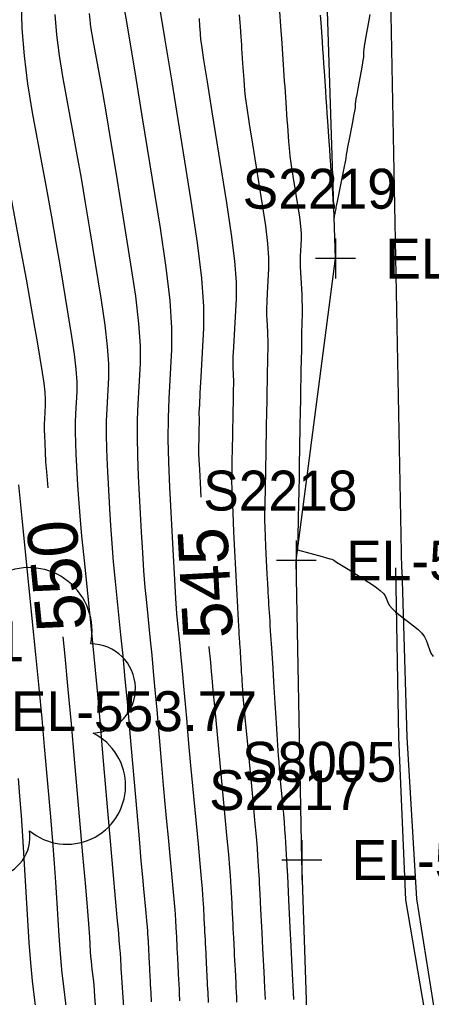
# Model space of a CAD drawing. Extents: x 1724534 to 1727318, y 657156 to 660047.
# Drawn here: x 1725500.6 to 1725541.9, y 658784.7 to 658882.6 of the extents above; entities that cross this region are included whole.
import ezdxf

# ---------------------------------------------------------------- set-up
doc = ezdxf.new("R2010")
doc.units = 0
for name, color, linetype in [('SURVEY - CONTOURS - Index with Text', 7, 'Continuous'), ('SURVEY - CONTOURS - Intermediate with optional Text', 7, 'Continuous'), ('SURVEY - DTM - Breaklines', 7, 'Continuous'), ('SURVEY - DTM - Breaklines - Points - Elevations', 7, 'Continuous'), ('SURVEY - DTM - Breaklines - Points - Locators', 7, 'Continuous'), ('SURVEY - DTM - Breaklines - Points - Numbers', 7, 'Continuous'), ('SURVEY - MISCELLANEOUS - Bottom of MH and CB - Points - Numbers', 7, 'Continuous'), ('SURVEY - UTILITIES - Electric (Underground) with Text', 7, 'Continuous'), ('SURVEY - UTILITIES - Fiber Optic Cable (Underground) with Text', 7, 'Continuous'), ('SURVEY - VEGETATION - Features - Points - Elevations', 7, 'Continuous'), ('SURVEY - VEGETATION - Features - Points - Numbers', 7, 'Continuous'), ('SURVEY - VEGETATION - Features with Text', 7, 'Continuous')]:
    doc.layers.add(name, color=color, linetype=linetype)

msp = doc.modelspace()

# ---------------------------------------------------------------- linework, layer by layer
at = {"layer": 'SURVEY - CONTOURS - Index with Text'}
for points in [[(1725497.421, 658883.779), (1725497.532, 658880.362), (1725497.804, 658876.878), (1725498.238, 658873.326), (1725498.833, 658869.706), (1725500.636, 658859.963), (1725501.251, 658856.622), (1725501.744, 658853.907), (1725502.114, 658851.818), (1725502.362, 658850.354), (1725502.859, 658847.284), (1725503.019, 658846.214), (1725503.125, 658845.305), (1725503.177, 658844.558), (1725503.176, 658843.973), (1725503.1, 658842.629), (1725503.08, 658842.099), (1725503.076, 658841.52), (1725503.089, 658840.891), (1725503.118, 658840.212), (1725503.217, 658838.334), (1725503.291, 658837.321), (1725503.432, 658835.734)], [(1725514.712, 658883.443), (1725515.174, 658880.583), (1725515.82, 658876.596), (1725517.787, 658864.461), (1725518.419, 658860.251), (1725518.842, 658856.721), (1725519.054, 658853.872), (1725519.056, 658851.703), (1725518.781, 658846.828), (1725518.691, 658845.218), (1725518.629, 658844.045), (1725518.593, 658843.31), (1725518.584, 658843.011), (1725518.596, 658842.799), (1725518.6, 658842.721), (1725518.603, 658842.645), (1725518.604, 658842.572), (1725518.603, 658842.502), (1725518.6, 658842.319), (1725518.598, 658842.249), (1725518.597, 658842.179), (1725518.596, 658842.106), (1725518.594, 658842.033), (1725518.591, 658841.835), (1725518.589, 658841.76), (1725518.588, 658841.683), (1725518.587, 658841.605), (1725518.585, 658841.525), (1725518.581, 658841.311), (1725518.58, 658841.229), (1725518.578, 658841.146), (1725518.577, 658841.061), (1725518.575, 658840.974), (1725518.571, 658840.741), (1725518.569, 658840.653), (1725518.568, 658840.562), (1725518.566, 658840.469), (1725518.564, 658840.375), (1725518.559, 658840.12), (1725518.558, 658840.023), (1725518.556, 658839.924), (1725518.554, 658839.823), (1725518.552, 658839.72), (1725518.547, 658839.44), (1725518.555, 658839.161), (1725518.582, 658838.534), (1725518.629, 658837.558), (1725518.696, 658836.234), (1725518.769, 658834.799)], [(1725504.937, 658820.809), (1725505.131, 658818.869), (1725505.452, 658815.535), (1725505.769, 658812.095), (1725506.084, 658808.551), (1725506.919, 658798.961), (1725507.197, 658795.747), (1725507.405, 658793.299), (1725507.543, 658791.616), (1725507.61, 658790.699), (1725507.694, 658789.273), (1725507.728, 658788.761), (1725507.765, 658788.293), (1725507.806, 658787.87), (1725507.851, 658787.491), (1725507.974, 658786.539), (1725508.036, 658785.918), (1725508.128, 658784.771), (1725508.252, 658783.096)], [(1725519.584, 658819.821), (1725519.629, 658819.379), (1725519.653, 658819.135), (1725519.679, 658818.864), (1725519.706, 658818.566), (1725519.735, 658818.24), (1725519.814, 658817.335), (1725519.873, 658816.685), (1725519.992, 658815.413), (1725520.171, 658813.52), (1725520.409, 658811.005), (1725521.124, 658803.471), (1725521.362, 658800.941), (1725521.54, 658799.002), (1725521.657, 658797.654), (1725521.715, 658796.898), (1725521.788, 658795.668), (1725521.812, 658795.264), (1725521.83, 658794.976), (1725521.84, 658794.802), (1725521.843, 658794.744), (1725521.843, 658794.743), (1725521.846, 658794.683), (1725521.855, 658794.505), (1725521.87, 658794.208), (1725521.891, 658793.794), (1725521.954, 658792.53), (1725521.978, 658792.056), (1725522.002, 658791.58), (1725522.026, 658791.104), (1725522.049, 658790.627), (1725522.113, 658789.353), (1725522.137, 658788.874), (1725522.161, 658788.395), (1725522.185, 658787.915), (1725522.209, 658787.434), (1725522.274, 658786.149), (1725522.298, 658785.667), (1725522.322, 658785.184), (1725522.346, 658784.7), (1725522.37, 658784.214)]]:
    msp.add_lwpolyline(points, dxfattribs=at)
at = {"layer": 'SURVEY - CONTOURS - Intermediate with optional Text'}
for points in [[(1725500.755, 658884.446), (1725500.843, 658881.746), (1725501.058, 658878.992), (1725501.401, 658876.185), (1725501.871, 658873.324), (1725503.296, 658865.623), (1725503.803, 658862.857), (1725504.253, 658860.332), (1725504.648, 658858.05), (1725504.987, 658856.011), (1725505.816, 658850.895), (1725506.083, 658849.111), (1725506.259, 658847.597), (1725506.346, 658846.352), (1725506.344, 658845.377), (1725506.217, 658843.136), (1725506.184, 658842.254), (1725506.177, 658841.288), (1725506.198, 658840.24), (1725506.247, 658839.108), (1725506.413, 658835.978), (1725506.5, 658834.628), (1725506.639, 658832.924), (1725506.827, 658830.867), (1725507.067, 658828.456), (1725507.772, 658821.555), (1725508.045, 658818.813), (1725508.335, 658815.763), (1725508.642, 658812.405), (1725508.967, 658808.738), (1725510.365, 658792.691), (1725510.506, 658791.098), (1725510.568, 658790.396), (1725510.633, 658789.711), (1725510.671, 658789.305), (1725510.682, 658789.182), (1725510.687, 658789.113), (1725510.694, 658789.002), (1725510.696, 658788.965), (1725510.699, 658788.918), (1725510.699, 658788.917), (1725510.699, 658788.912), (1725510.7, 658788.896), (1725510.709, 658788.716), (1725510.711, 658788.673), (1725510.713, 658788.63), (1725510.715, 658788.587), (1725510.726, 658788.384), (1725510.728, 658788.34), (1725510.73, 658788.297), (1725510.732, 658788.253), (1725510.742, 658788.048), (1725510.745, 658788.004), (1725510.747, 658787.96), (1725510.753, 658787.843), (1725510.759, 658787.71), (1725510.762, 658787.665), (1725510.767, 658787.546), (1725510.792, 658787.179), (1725511.134, 658782.202)], [(1725510.985, 658884.176), (1725511.276, 658882.603), (1725511.457, 658881.559), (1725511.782, 658879.608), (1725512.251, 658876.748), (1725512.863, 658872.982), (1725514.688, 658861.726), (1725515.274, 658857.802), (1725515.662, 658854.471), (1725515.853, 658851.732), (1725515.848, 658849.587), (1725515.57, 658844.657), (1725515.496, 658842.716), (1725515.482, 658840.592), (1725515.528, 658838.286), (1725515.635, 658835.795), (1725516, 658828.91), (1725516.13, 658826.549), (1725516.247, 658824.628), (1725516.351, 658823.148), (1725516.441, 658822.108), (1725516.665, 658819.923), (1725516.751, 658819.055), (1725516.843, 658818.089), (1725516.94, 658817.026), (1725517.043, 658815.865), (1725517.324, 658812.639), (1725517.442, 658811.308), (1725517.586, 658809.733), (1725517.755, 658807.915), (1725517.949, 658805.853), (1725518.501, 658800.031), (1725518.685, 658798.076), (1725518.822, 658796.578), (1725518.913, 658795.536), (1725518.958, 658794.951), (1725519.015, 658794.001), (1725519.033, 658793.689), (1725519.047, 658793.466), (1725519.055, 658793.333), (1725519.057, 658793.288), (1725519.057, 658793.286), (1725519.06, 658793.24), (1725519.067, 658793.102), (1725519.078, 658792.873), (1725519.094, 658792.553), (1725519.143, 658791.577), (1725519.161, 658791.21), (1725519.18, 658790.843), (1725519.198, 658790.475), (1725519.216, 658790.106), (1725519.266, 658789.121), (1725519.284, 658788.752), (1725519.303, 658788.382), (1725519.321, 658788.01), (1725519.34, 658787.639), (1725519.39, 658786.646), (1725519.408, 658786.273), (1725519.427, 658785.9), (1725519.446, 658785.526), (1725519.465, 658785.151), (1725519.515, 658784.15)], [(1725504.153, 658883.129), (1725504.312, 658881.106), (1725504.564, 658879.043), (1725504.909, 658876.941), (1725505.956, 658871.283), (1725506.354, 658869.091), (1725506.763, 658866.757), (1725507.182, 658864.283), (1725507.612, 658861.668), (1725508.774, 658854.505), (1725509.146, 658852.008), (1725509.394, 658849.888), (1725509.515, 658848.145), (1725509.512, 658846.78), (1725509.335, 658843.643), (1725509.288, 658842.408), (1725509.279, 658841.056), (1725509.308, 658839.588), (1725509.376, 658838.004), (1725509.609, 658833.622), (1725509.71, 658831.935), (1725509.841, 658830.159), (1725510.002, 658828.294), (1725510.191, 658826.34), (1725510.736, 658821.011), (1725510.947, 658818.893), (1725511.171, 658816.538), (1725511.408, 658813.945), (1725511.659, 658811.114), (1725512.344, 658803.247), (1725512.58, 658800.553), (1725512.772, 658798.372), (1725512.922, 658796.704), (1725513.029, 658795.548), (1725513.256, 658793.151), (1725513.332, 658792.346), (1725513.388, 658791.729), (1725513.426, 658791.3), (1725513.444, 658791.059), (1725513.467, 658790.668), (1725513.475, 658790.54), (1725513.481, 658790.448), (1725513.484, 658790.393), (1725513.485, 658790.374), (1725513.485, 658790.374), (1725513.486, 658790.355), (1725513.489, 658790.298), (1725513.493, 658790.204), (1725513.5, 658790.072), (1725513.52, 658789.67), (1725513.528, 658789.519), (1725513.535, 658789.368), (1725513.543, 658789.216), (1725513.551, 658789.064), (1725513.571, 658788.659), (1725513.578, 658788.507), (1725513.586, 658788.354), (1725513.594, 658788.201), (1725513.601, 658788.048), (1725513.622, 658787.639), (1725513.63, 658787.486), (1725513.637, 658787.332), (1725513.645, 658787.178), (1725513.653, 658787.024), (1725513.673, 658786.612), (1725513.681, 658786.457), (1725513.689, 658786.302), (1725513.697, 658786.147), (1725513.704, 658785.991), (1725513.725, 658785.575), (1725513.751, 658785.162), (1725513.813, 658784.233)], [(1725507.565, 658883.219), (1725507.726, 658881.901), (1725507.947, 658880.558), (1725508.616, 658876.943), (1725508.906, 658875.325), (1725509.273, 658873.183), (1725509.717, 658870.516), (1725510.238, 658867.325), (1725511.731, 658858.116), (1725512.21, 658854.905), (1725512.528, 658852.179), (1725512.684, 658849.939), (1725512.68, 658848.184), (1725512.452, 658844.15), (1725512.392, 658842.562), (1725512.38, 658840.824), (1725512.418, 658838.937), (1725512.506, 658836.899), (1725512.804, 658831.266), (1725512.92, 658829.242), (1725513.044, 658827.393), (1725513.176, 658825.721), (1725513.316, 658824.224), (1725513.701, 658820.467), (1725513.849, 658818.974), (1725514.007, 658817.314), (1725514.174, 658815.485), (1725514.351, 658813.489), (1725514.834, 658807.943), (1725515.011, 658805.93), (1725515.179, 658804.052), (1725515.338, 658802.309), (1725515.489, 658800.701), (1725516.008, 658795.211), (1725516.105, 658794.153), (1725516.17, 658793.418), (1725516.201, 658793.005), (1725516.241, 658792.335), (1725516.254, 658792.115), (1725516.264, 658791.957), (1725516.269, 658791.863), (1725516.271, 658791.831), (1725516.271, 658791.83), (1725516.273, 658791.797), (1725516.278, 658791.7), (1725516.286, 658791.539), (1725516.297, 658791.312), (1725516.332, 658790.623), (1725516.37, 658789.845), (1725516.384, 658789.585), (1725516.431, 658788.629), (1725516.444, 658788.368), (1725516.458, 658788.106), (1725516.471, 658787.843), (1725516.506, 658787.143), (1725516.519, 658786.88), (1725516.532, 658786.616), (1725516.545, 658786.352), (1725516.559, 658786.087), (1725516.594, 658785.381), (1725516.607, 658785.116), (1725516.647, 658784.317)], [(1725522.637, 658883.116), (1725522.69, 658882.338), (1725522.716, 658881.946), (1725522.788, 658880.898), (1725522.815, 658880.504), (1725522.842, 658880.109), (1725522.869, 658879.711), (1725522.896, 658879.311), (1725522.969, 658878.242), (1725522.997, 658877.84), (1725523.024, 658877.436), (1725523.052, 658877.029), (1725523.08, 658876.621), (1725523.154, 658875.53), (1725523.225, 658874.887), (1725523.381, 658873.776), (1725523.622, 658872.197), (1725523.949, 658870.151), (1725524.935, 658864.072), (1725525.252, 658861.962), (1725525.464, 658860.194), (1725525.57, 658858.766), (1725525.571, 658857.68), (1725525.433, 658855.237), (1725525.391, 658854.381), (1725525.368, 658853.646), (1725525.365, 658853.031), (1725525.38, 658852.537), (1725525.447, 658851.38), (1725525.469, 658850.954), (1725525.482, 658850.543), (1725525.487, 658850.146), (1725525.484, 658849.764), (1725525.466, 658848.766), (1725525.459, 658848.388), (1725525.452, 658848.003), (1725525.445, 658847.61), (1725525.437, 658847.209), (1725525.418, 658846.131), (1725525.41, 658845.722), (1725525.403, 658845.305), (1725525.395, 658844.88), (1725525.387, 658844.446), (1725525.365, 658843.277), (1725525.341, 658841.919), (1725525.332, 658841.447), (1725525.3, 658839.694), (1725525.291, 658839.201), (1725525.282, 658838.698), (1725525.272, 658838.183), (1725525.247, 658836.796), (1725525.237, 658836.269), (1725525.227, 658835.73), (1725525.217, 658835.179), (1725525.207, 658834.615), (1725525.179, 658833.095), (1725525.177, 658832.465), (1725525.19, 658831.716), (1725525.22, 658830.847), (1725525.265, 658829.859), (1725525.408, 658827.064), (1725525.455, 658826.146), (1725525.488, 658825.491), (1725525.508, 658825.096), (1725525.515, 658824.964), (1725525.515, 658824.959), (1725525.519, 658824.901), (1725525.53, 658824.728), (1725525.549, 658824.442), (1725525.574, 658824.041), (1725525.652, 658822.822), (1725525.682, 658822.361), (1725525.712, 658821.894), (1725525.742, 658821.419), (1725525.773, 658820.938), (1725525.855, 658819.646), (1725525.887, 658819.158), (1725525.951, 658818.159), (1725525.983, 658817.649), (1725526.071, 658816.277), (1725526.104, 658815.759), (1725526.138, 658815.233), (1725526.172, 658814.698), (1725526.207, 658814.155), (1725526.3, 658812.697), (1725526.335, 658812.146), (1725526.371, 658811.586), (1725526.408, 658811.017), (1725526.544, 658808.886), (1725526.586, 658808.271), (1725526.64, 658807.593), (1725526.703, 658806.85), (1725526.777, 658806.044), (1725526.99, 658803.808), (1725527.064, 658802.991), (1725527.129, 658802.215), (1725527.184, 658801.481), (1725527.229, 658800.79), (1725527.335, 658799.001), (1725527.371, 658798.414), (1725527.396, 658797.994), (1725527.411, 658797.742), (1725527.416, 658797.658), (1725527.416, 658797.655), (1725527.42, 658797.568), (1725527.433, 658797.309), (1725527.455, 658796.878), (1725527.577, 658794.437), (1725527.611, 658793.747), (1725527.646, 658793.055), (1725527.681, 658792.363), (1725527.715, 658791.668), (1725527.808, 658789.815), (1725527.843, 658789.12), (1725527.878, 658788.423), (1725527.913, 658787.724), (1725527.948, 658787.024), (1725528.041, 658785.156), (1725528.077, 658784.454)], [(1725526.673, 658883.437), (1725526.774, 658881.95), (1725526.889, 658880.265), (1725526.928, 658879.697), (1725527.07, 658877.609), (1725527.11, 658877.036), (1725527.149, 658876.46), (1725527.188, 658875.88), (1725527.294, 658874.332), (1725527.334, 658873.749), (1725527.374, 658873.164), (1725527.414, 658872.576), (1725527.454, 658871.985), (1725527.562, 658870.404), (1725527.621, 658869.742), (1725527.716, 658868.942), (1725527.847, 658868.005), (1725528.014, 658866.929), (1725528.509, 658863.877), (1725528.668, 658862.818), (1725528.774, 658861.93), (1725528.828, 658861.213), (1725528.828, 658860.668), (1725528.759, 658859.441), (1725528.741, 658858.963), (1725528.738, 658858.446), (1725528.75, 658857.892), (1725528.778, 658857.3), (1725528.873, 658855.671), (1725528.903, 658855.071), (1725528.921, 658854.491), (1725528.929, 658853.933), (1725528.925, 658853.395), (1725528.899, 658851.99), (1725528.889, 658851.458), (1725528.869, 658850.361), (1725528.859, 658849.797), (1725528.831, 658848.279), (1725528.82, 658847.704), (1725528.81, 658847.116), (1725528.799, 658846.517), (1725528.788, 658845.906), (1725528.757, 658844.26), (1725528.746, 658843.636), (1725528.734, 658842.999), (1725528.722, 658842.348), (1725528.665, 658839.215), (1725528.652, 658838.521), (1725528.626, 658837.087), (1725528.59, 658835.133), (1725528.577, 658834.414), (1725528.565, 658833.722), (1725528.552, 658833.057), (1725528.541, 658832.419), (1725528.487, 658829.503), (1725530.935, 658828.833), (1725531.395, 658828.707), (1725531.724, 658828.616), (1725531.923, 658828.561), (1725531.992, 658828.541), (1725532.101, 658828.472), (1725532.39, 658828.29), (1725533.539, 658827.566), (1725535.577, 658826.281), (1725536.259, 658825.828), (1725536.773, 658825.436), (1725537.121, 658825.103), (1725537.302, 658824.83), (1725537.563, 658824.182), (1725537.712, 658823.921), (1725537.962, 658823.626), (1725538.314, 658823.296), (1725538.767, 658822.931), (1725540.111, 658821.912), (1725540.568, 658821.533), (1725540.93, 658821.164), (1725541.197, 658820.802), (1725541.37, 658820.449), (1725541.703, 658819.517), (1725541.856, 658819.174), (1725542.065, 658818.841)], [(1725530.756, 658883.075), (1725530.805, 658882.346), (1725530.938, 658880.399), (1725530.988, 658879.667), (1725531.038, 658878.931), (1725531.089, 658878.191), (1725531.14, 658877.448), (1725531.275, 658875.461), (1725531.326, 658874.714), (1725531.377, 658873.963), (1725531.429, 658873.208), (1725531.481, 658872.45), (1725531.619, 658870.422), (1725531.671, 658869.659), (1725531.723, 658868.893), (1725531.776, 658868.122), (1725531.829, 658867.348), (1725531.97, 658865.278), (1725532.017, 658864.597), (1725532.05, 658864.109), (1725532.071, 658863.812), (1725532.079, 658863.706), (1725532.083, 658863.682), (1725532.084, 658863.673), (1725532.085, 658863.666), (1725532.086, 658863.66), (1725532.086, 658863.656), (1725532.085, 658863.646), (1725532.086, 658863.63), (1725532.088, 658863.588), (1725532.092, 658863.521), (1725532.097, 658863.43), (1725532.113, 658863.151), (1725532.119, 658863.056), (1725532.123, 658862.981), (1725532.127, 658862.924), (1725532.13, 658862.887), (1725532.142, 658862.757), (1725532.283, 658863.407), (1725532.309, 658863.528), (1725532.328, 658863.616), (1725532.339, 658863.668), (1725532.343, 658863.686), (1725532.343, 658863.687), (1725532.343, 658863.689), (1725532.343, 658863.692), (1725532.343, 658863.698), (1725532.343, 658863.706), (1725532.344, 658863.729), (1725532.364, 658863.83), (1725532.421, 658864.116), (1725532.517, 658864.586), (1725532.651, 658865.241), (1725533.059, 658867.233), (1725533.193, 658867.893), (1725533.289, 658868.38), (1725533.348, 658868.694), (1725533.368, 658868.835), (1725533.373, 658868.979), (1725533.392, 658869.114), (1725533.444, 658869.411), (1725533.53, 658869.87), (1725533.65, 658870.49), (1725534.015, 658872.359), (1725534.135, 658872.984), (1725534.221, 658873.459), (1725534.274, 658873.782), (1725534.294, 658873.954), (1725534.302, 658874.21), (1725534.32, 658874.377), (1725534.367, 658874.684), (1725534.445, 658875.131), (1725534.552, 658875.72), (1725534.879, 658877.476), (1725534.986, 658878.069), (1725535.064, 658878.531), (1725535.112, 658878.862), (1725535.131, 658879.063), (1725535.14, 658879.424), (1725535.157, 658879.62), (1725535.201, 658879.936), (1725535.271, 658880.374), (1725535.367, 658880.932), (1725535.66, 658882.583), (1725535.757, 658883.146)], [(1725518.604, 658882.741), (1725518.659, 658881.93), (1725518.675, 658881.707), (1725518.746, 658880.656), (1725518.829, 658880.031), (1725519.046, 658878.61), (1725519.398, 658876.39), (1725519.884, 658873.374), (1725521.361, 658864.267), (1725521.836, 658861.107), (1725522.153, 658858.458), (1725522.312, 658856.319), (1725522.313, 658854.692), (1725522.107, 658851.032), (1725522.041, 658849.799), (1725521.998, 658848.845), (1725521.979, 658848.17), (1725521.982, 658847.774), (1725522.022, 658847.09), (1725522.034, 658846.837), (1725522.042, 658846.594), (1725522.045, 658846.359), (1725522.044, 658846.133), (1725522.033, 658845.543), (1725522.029, 658845.319), (1725522.025, 658845.091), (1725522.02, 658844.858), (1725522.016, 658844.621), (1725522.004, 658843.983), (1725522, 658843.741), (1725521.991, 658843.242), (1725521.986, 658842.985), (1725521.973, 658842.294), (1725521.969, 658842.032), (1725521.964, 658841.764), (1725521.954, 658841.211), (1725521.94, 658840.459), (1725521.935, 658840.173), (1725521.929, 658839.882), (1725521.924, 658839.584), (1725521.903, 658838.458), (1725521.897, 658838.146), (1725521.892, 658837.827), (1725521.88, 658837.167), (1725521.863, 658836.268), (1725521.871, 658835.706), (1725521.908, 658834.694), (1725521.974, 658833.234), (1725522.069, 658831.324), (1725522.359, 658825.633), (1725522.455, 658823.765), (1725522.523, 658822.431), (1725522.577, 658821.363), (1725522.577, 658821.361), (1725522.579, 658821.339), (1725522.583, 658821.274), (1725522.59, 658821.165), (1725522.629, 658820.552), (1725522.64, 658820.377), (1725522.652, 658820.2), (1725522.663, 658820.02), (1725522.675, 658819.838), (1725522.706, 658819.348), (1725522.718, 658819.163), (1725522.742, 658818.785), (1725522.755, 658818.592), (1725522.788, 658818.072), (1725522.813, 658817.676), (1725522.839, 658817.268), (1725522.875, 658816.716), (1725522.888, 658816.507), (1725522.901, 658816.295), (1725522.915, 658816.079), (1725522.967, 658815.271), (1725523.006, 658814.8), (1725523.094, 658813.826), (1725523.231, 658812.351), (1725523.418, 658810.374), (1725523.981, 658804.432), (1725524.171, 658802.411), (1725524.315, 658800.807), (1725524.416, 658799.617), (1725524.472, 658798.844), (1725524.562, 658797.334), (1725524.613, 658796.485), (1725524.625, 658796.272), (1725524.633, 658796.125), (1725524.662, 658795.543), (1725524.688, 658795.034), (1725524.766, 658793.483), (1725524.795, 658792.901), (1725524.824, 658792.318), (1725524.853, 658791.733), (1725524.882, 658791.148), (1725524.961, 658789.584), (1725524.99, 658788.997), (1725525.049, 658787.82), (1725525.079, 658787.229), (1725525.157, 658785.652), (1725525.187, 658785.061), (1725525.217, 658784.468)], [(1725500.478, 658836.012), (1725500.817, 658832.687), (1725501.844, 658822.643), (1725502.209, 658819.016), (1725502.536, 658815.671), (1725502.825, 658812.607), (1725503.074, 658809.823), (1725503.688, 658802.775), (1725503.9, 658800.284), (1725504.076, 658798.098), (1725504.215, 658796.216), (1725504.318, 658794.639), (1725504.545, 658790.838), (1725504.634, 658789.472), (1725504.734, 658788.224), (1725504.843, 658787.094), (1725504.961, 658786.083), (1725505.29, 658783.545)], [(1725500.457, 658806.59), (1725500.603, 658804.822), (1725500.747, 658802.897), (1725500.888, 658800.816), (1725501.027, 658798.578), (1725501.395, 658792.402), (1725501.541, 658790.182), (1725501.702, 658788.154), (1725501.879, 658786.319), (1725502.072, 658784.676), (1725502.607, 658780.551)]]:
    msp.add_lwpolyline(points, dxfattribs=at)
at = {"layer": 'SURVEY - DTM - Breaklines'}
msp.add_lwpolyline([(1725533.454, 658738.584), (1725529.91, 658768.444), (1725528.895, 658798.433), (1725528.35, 658828.444), (1725532.274, 658858.683), (1725531.303, 658888.673), (1725527.687, 658918.53), (1725523.837, 658948.374), (1725524.63, 658981.767), (1725524.814, 658996.206), (1725524.72, 658997.154)], dxfattribs=at)
at = {"layer": 'SURVEY - DTM - Breaklines - Points - Locators'}
for p, q in [((1725532.274, 658860.683), (1725532.274, 658856.683)), ((1725534.274, 658858.683), (1725530.274, 658858.683)), ((1725528.35, 658830.444), (1725528.35, 658826.444)), ((1725530.35, 658828.444), (1725526.35, 658828.444)), ((1725528.895, 658800.433), (1725528.895, 658796.433)), ((1725530.895, 658798.433), (1725526.895, 658798.433))]:
    msp.add_line(p, q, dxfattribs=at)
at = {"layer": 'SURVEY - UTILITIES - Electric (Underground) with Text'}
msp.add_lwpolyline([(1725538.314, 658827.699), (1725538.61, 658810.76), (1725539.309, 658794.446), (1725544.796, 658762.344), (1725548.909, 658731.403), (1725555.845, 658694.728), (1725557.583, 658674.802)], dxfattribs=at)
at = {"layer": 'SURVEY - UTILITIES - Fiber Optic Cable (Underground) with Text'}
msp.add_line((1725538.949, 658827.551), (1725533.816, 659093.214), dxfattribs=at)
msp.add_lwpolyline([(1725538.949, 658827.551), (1725539.433, 658810.741), (1725540.407, 658794.551), (1725545.54, 658762.23), (1725549.453, 658731.328), (1725556.372, 658694.759), (1725557.942, 658674.857)], dxfattribs=at)
at = {"layer": 'SURVEY - VEGETATION - Features with Text'}
for centre, radius, start, end in [((1725501.537, 658821.394), 6.334, 348.1042, 114.94987), ((1725507.746, 658815.618), 4.471, 272.81715, 90.13629), ((1725505.355, 658805.889), 5.875, 230.19848, 63.61817), ((1725497.602, 658800.748), 4.041, 190.17779, 8.92343)]:
    msp.add_arc(centre, radius, start, end, dxfattribs=at)

# ---------------------------------------------------------------- texts
at = {"layer": 'SURVEY - CONTOURS - Index with Text'}
for s, rotation, p in [('550', 95.75907, (1725507.361, 658821.61)), ('545', 93.11193, (1725522.018, 658820.724))]:
    msp.add_text(s, height=5, rotation=rotation, dxfattribs=at).set_placement(p)
at = {"layer": 'SURVEY - DTM - Breaklines - Points - Elevations'}
for s, p in [('EL-541.04', (1725537.274, 658856.683)), ('EL-542.03', (1725533.35, 658826.444)), ('EL-542.47', (1725533.895, 658796.433))]:
    msp.add_text(s, height=4, dxfattribs=at).set_placement(p)
at = {"layer": 'SURVEY - DTM - Breaklines - Points - Numbers'}
for s, p in [('S2219', (1725522.971, 658863.683)), ('S2218', (1725519.015, 658833.444)), ('S2217', (1725519.607, 658803.433))]:
    msp.add_text(s, height=4, dxfattribs=at).set_placement(p)
at = {"layer": 'SURVEY - MISCELLANEOUS - Bottom of MH and CB - Points - Numbers'}
msp.add_text('S8005', height=4, dxfattribs=at).set_placement((1725522.905, 658806.276))
at = {"layer": 'SURVEY - VEGETATION - Features - Points - Elevations'}
msp.add_text('EL-553.77', height=4, dxfattribs=at).set_placement((1725499.731, 658811.349))
at = {"layer": 'SURVEY - VEGETATION - Features - Points - Numbers'}
msp.add_text('S2141', height=4, dxfattribs=at).set_placement((1725485.601, 658818.349))

doc.saveas('drawing.dxf')
